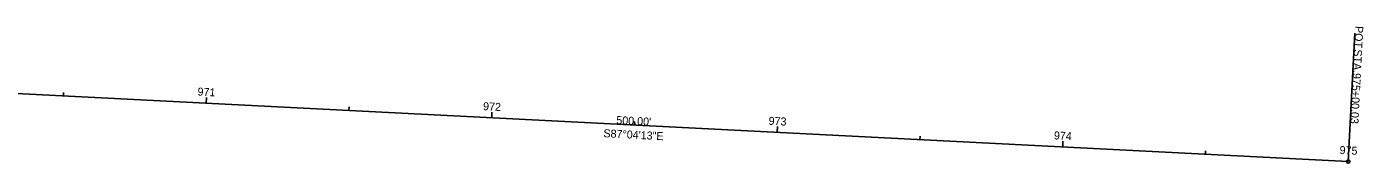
# Model space of a CAD drawing. Extents: x 2061744 to 2069155, y 709240 to 710416.
# Drawn here: x 2068687.3 to 2069154.8, y 709240.4 to 709288.1 of the extents above; entities that cross this region are included whole.
import ezdxf

# ---------------------------------------------------------------- set-up
doc = ezdxf.new("R2010")
doc.units = 0
for name, color, linetype in [('RS_Raster1', 7, 'Continuous'), ('RW_X_CL', 7, 'Continuous'), ('RW_X_CL_100_Bearings', 7, 'Continuous'), ('RW_X_CL_100_Cardinal_Points', 7, 'Continuous'), ('RW_X_CL_100_Distances', 7, 'Continuous'), ('RW_X_CL_100_Stations', 7, 'Continuous')]:
    doc.layers.add(name, color=color, linetype=linetype)

msp = doc.modelspace()

# ---------------------------------------------------------------- linework, layer by layer
at = {"layer": 'RS_Raster1'}
msp.add_line((2068650.24, 709266.54), (2069149.58, 709240.99), dxfattribs=at)
at = {"layer": 'RW_X_CL'}
msp.add_line((2068650.24, 709266.54), (2069149.58, 709240.99), dxfattribs=at)
at = {"layer": 'RW_X_CL_100_Cardinal_Points'}
msp.add_line((2069149.58, 709240.99), (2069151.88, 709285.93), dxfattribs=at)
msp.add_circle((2069149.58, 709240.99), 0.6, dxfattribs=at)
at = {"layer": 'RW_X_CL_100_Stations'}
for p, q in [((2068700.14, 709263.99), (2068700.2, 709265.19)), ((2068750.08, 709261.43), (2068750.18, 709263.43)), ((2068800.01, 709258.88), (2068800.07, 709260.08)), ((2068849.95, 709256.32), (2068850.05, 709258.32)), ((2068899.88, 709253.77), (2068899.94, 709254.97)), ((2068949.82, 709251.21), (2068949.92, 709253.21)), ((2068999.75, 709248.66), (2068999.81, 709249.85)), ((2069049.69, 709246.1), (2069049.79, 709248.1)), ((2069099.62, 709243.54), (2069099.68, 709244.74)), ((2069149.56, 709240.99), (2069149.66, 709242.99))]:
    msp.add_line(p, q, dxfattribs=at)

# ---------------------------------------------------------------- texts
at = {"layer": 'RW_X_CL_100_Bearings'}
msp.add_text('S87°04\'13"E', height=2.8, rotation=357.0704, dxfattribs=at).set_placement((2068888.97, 709249.52))
at = {"layer": 'RW_X_CL_100_Cardinal_Points'}
for s, p in [('POT', (2069152.05, 709288.46)), (' STA. ', (2069151.68, 709281.34)), ('975+00.03', (2069151.21, 709272.02))]:
    msp.add_text(s, height=2.8, rotation=267.0704, dxfattribs=at).set_placement(p)
at = {"layer": 'RW_X_CL_100_Distances'}
msp.add_text("500.00'", height=2.8, rotation=357.0704, dxfattribs=at).set_placement((2068893.48, 709254.13))
at = {"layer": 'RW_X_CL_100_Stations'}
for s, p in [('971', (2068746.99, 709264.09)), ('972', (2068846.87, 709258.98)), ('973', (2068946.75, 709253.87)), ('974', (2069046.54, 709248.76)), ('975', (2069146.48, 709243.65))]:
    msp.add_text(s, height=2.8, rotation=357.0704, dxfattribs=at).set_placement(p)

doc.saveas('drawing.dxf')
